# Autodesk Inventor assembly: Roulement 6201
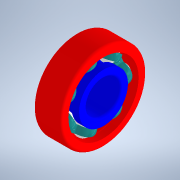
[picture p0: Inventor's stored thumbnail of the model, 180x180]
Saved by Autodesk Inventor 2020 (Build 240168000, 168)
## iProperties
Created: 2003-06
Part Number: Roulement 6201
Document SubType Name: Assembly
Designer: Bruno
Author: Bruno
Sending System: SolidWorks 2011
Last Author: Professeur
Last Saved: 2014-11-10
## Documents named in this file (5)
- D:\Téléchargements-2016-17\scoot_elec\pièces à assembler\ROULEMENT 6201\Roulement 6201.iam
- D:\Téléchargements-2016-17\scoot_elec\pièces à assembler\ROULEMENT 6201\Bague intéreure 6201.ipt
- D:\Téléchargements-2016-17\scoot_elec\pièces à assembler\ROULEMENT 6201\Billes 6201.ipt
- D:\Téléchargements-2016-17\scoot_elec\pièces à assembler\ROULEMENT 6201\Cage 6201.ipt
- D:\Téléchargements-2016-17\scoot_elec\pièces à assembler\ROULEMENT 6201\Bague extérieure 6201.ipt
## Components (10 placed, 4 different names)
1. Bague intéreure 6201:1
2. Billes 6201:1
3. Cage 6201:1
4. Billes 6201:2
5. Billes 6201:3
6. Billes 6201:4
7. Billes 6201:5
8. Billes 6201:6
9. Billes 6201:7
10. Bague extérieure 6201:1
